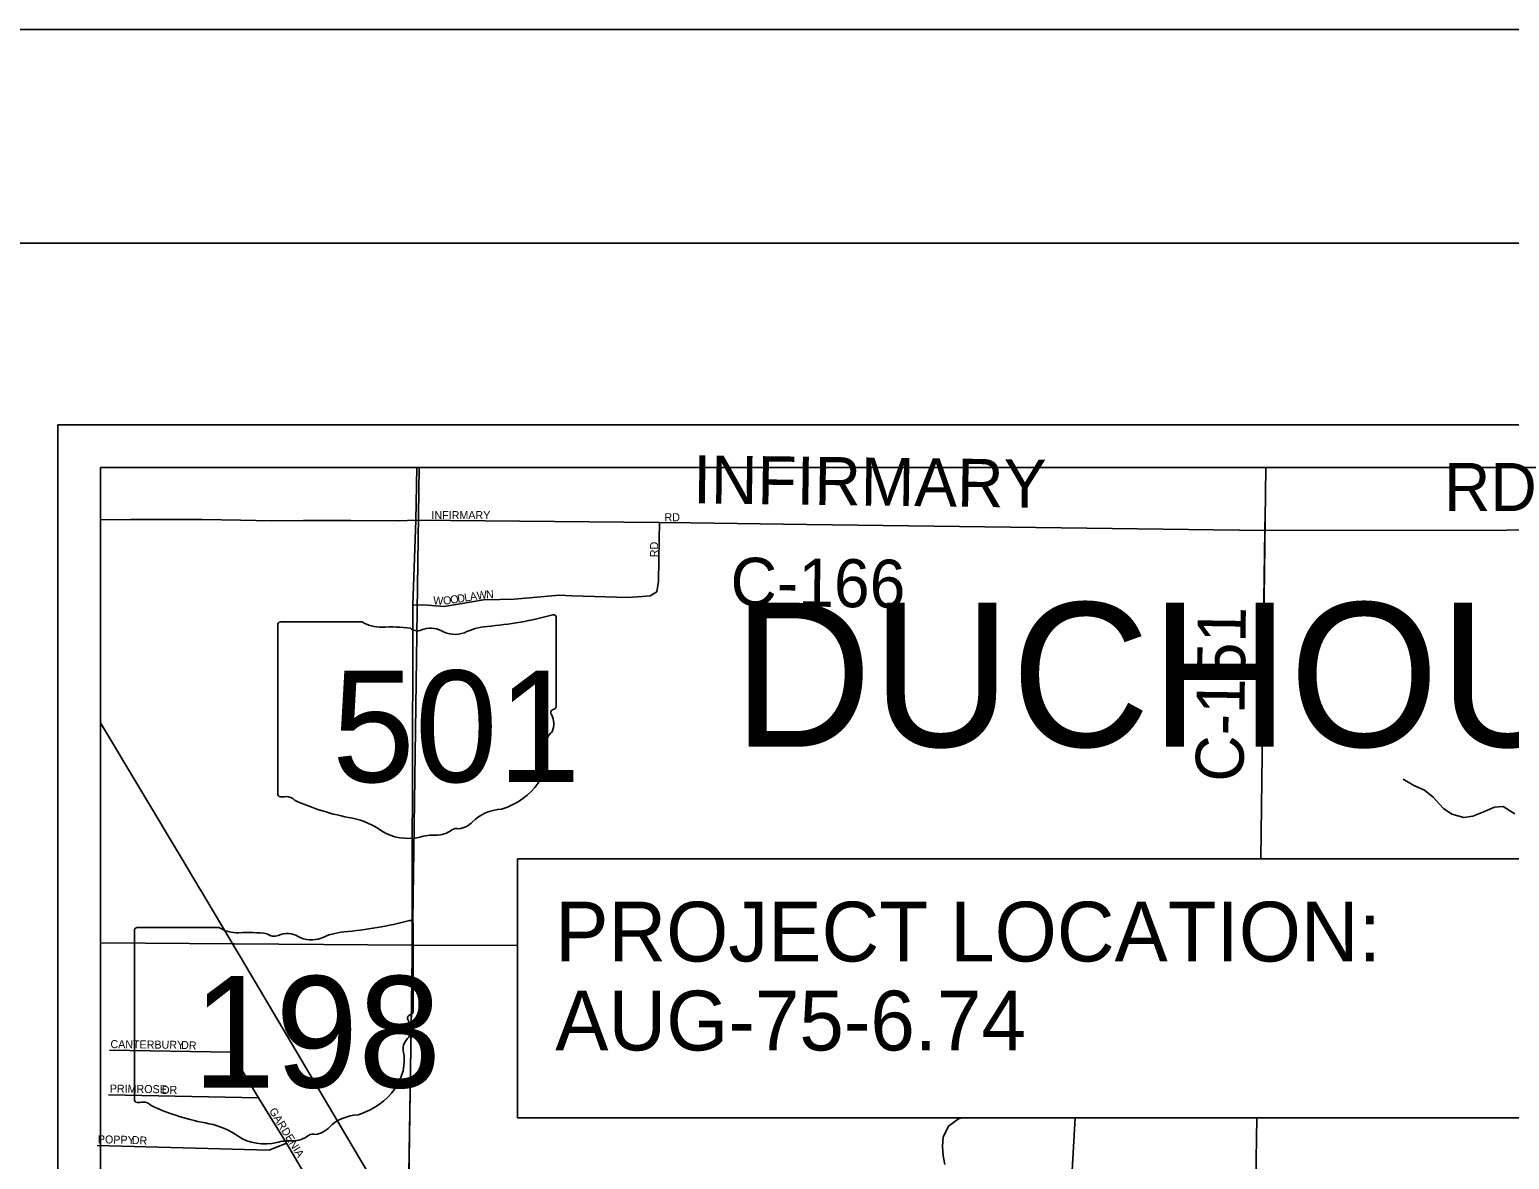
# Model space of a CAD drawing. Extents: x -784 to 1375, y -225 to 440.
# Drawn here: x 63.8 to 133.1, y 387.1 to 440 of the extents above; entities that cross this region are included whole.
import ezdxf

# ---------------------------------------------------------------- set-up
doc = ezdxf.new("R2010")
doc.units = 0
for name, color, linetype in [('GM_X_City_Street', 7, 'Continuous'), ('GM_X_City_Street_Text', 7, 'Continuous'), ('GM_X_County_Road', 7, 'Continuous'), ('GM_X_County_Road_Text', 7, 'Continuous'), ('GM_X_Minor_River', 7, 'Continuous'), ('GM_X_Section', 7, 'Continuous'), ('GM_X_State_Location', 7, 'Continuous'), ('GM_X_State_Route', 7, 'Continuous'), ('GM_X_State_Shield', 7, 'Continuous'), ('GM_X_Township_Text', 7, 'Continuous'), ('SH_Border', 7, 'Continuous'), ('SH_Cut_Line', 7, 'Continuous'), ('SH_Data', 7, 'Continuous'), ('SH_Text', 7, 'Continuous')]:
    doc.layers.add(name, color=color, linetype=linetype)

msp = doc.modelspace()

# ---------------------------------------------------------------- linework, layer by layer
at = {"layer": 'GM_X_City_Street'}
for points in [[(81.06, 416.992), (81.861, 417.014)], [(81.721, 413.038), (82.22, 413.047), (83.192, 412.978), (83.938, 413.102), (85.024, 413.284), (85.799, 413.305), (86.464, 413.316), (87.718, 413.425), (88.569, 413.502), (89.19, 413.469), (91.799, 413.399), (92.473, 413.447), (92.844, 413.48), (93.161, 413.665), (93.226, 414.167), (93.27, 416.098), (93.281, 416.916)], [(81.861, 417.014), (81.861, 417.014), (91.612, 416.93)], [(91.612, 416.93), (93.281, 416.916), (94.732, 416.896)], [(67.507, 392.196), (73.204, 392.102)], [(78.997, 382.464), (77.542, 384.845), (75.795, 387.841), (74.481, 389.954), (73.204, 392.102)], [(67.448, 390.092), (74.481, 389.954)], [(112.107, 376.784), (112.133, 377.221), (112.296, 380.735), (112.591, 386.006), (112.762, 389.014)], [(66.931, 387.726), (74.98, 387.509), (75.795, 387.841)]]:
    msp.add_lwpolyline(points, dxfattribs=at)
at = {"layer": 'GM_X_County_Road'}
for points in [[(67.088, 417.032), (68.489, 417.046), (71.597, 417.057), (71.842, 417.052)], [(71.842, 417.052), (73.637, 417.014), (75.088, 416.981), (76.593, 417.003), (78.818, 417.003), (81.043, 416.992), (81.06, 416.992)], [(94.732, 416.896), (100.192, 416.823)], [(100.192, 416.823), (121.642, 416.536)], [(121.642, 416.536), (121.649, 416.944)], [(121.512, 406.704), (121.513, 406.783), (121.642, 416.536)], [(121.642, 416.536), (155.683, 416.584)]]:
    msp.add_lwpolyline(points, dxfattribs=at)
at = {"layer": 'GM_X_Minor_River'}
for points in [[(133.369, 403.256), (132.818, 403.609), (132.412, 403.569), (131.868, 403.336), (131.4, 403.148), (130.978, 403.093), (130.41, 403.251), (130.023, 403.512), (129.534, 404.044), (129.133, 404.364), (128.625, 404.582), (128.134, 404.889)], [(106.651, 386.832), (106.581, 387.238), (106.542, 387.689), (106.578, 388.109), (106.825, 388.631), (107.296, 388.97), (107.444, 389.014)]]:
    msp.add_lwpolyline(points, dxfattribs=at)
at = {"layer": 'GM_X_Section'}
for p, q in [((121.69, 419.485), (121.464, 401.16)), ((121.464, 401.16), (121.69, 419.485))]:
    msp.add_line(p, q, dxfattribs=at)
for points in [[(82.01, 419.485), (81.709, 397.114), (67.088, 397.216)], [(86.63, 397.087), (81.709, 397.114), (82.01, 419.485)], [(67.088, 397.216), (81.709, 397.114), (81.068, 357.283), (71.441, 357.464), (71.653, 357.594), (72.121, 357.736), (72.758, 358.099), (73.273, 358.374), (73.924, 358.677), (74.439, 358.982), (75.353, 359.701), (76.082, 360.182), (77.094, 360.568), (77.592, 360.724), (77.925, 360.897), (78.122, 386.365), (67.088, 386.554)], [(121.281, 389.014), (120.755, 357.05), (81.068, 357.283), (81.709, 397.114), (86.63, 397.087)], [(133.637, 396.836), (161.159, 396.705), (160.697, 356.887), (120.755, 357.05), (121.281, 389.014)]]:
    msp.add_lwpolyline(points, dxfattribs=at)
at = {"layer": 'GM_X_State_Route'}
for p, q in [((81.875, 417.813), (81.905, 419.485)), ((70.956, 401.053), (67.088, 407.532))]:
    msp.add_line(p, q, dxfattribs=at)
for points in [[(81.717, 411.456), (81.718, 411.633), (81.721, 413.038), (81.861, 417.014), (81.875, 417.813)], [(81.691, 400.382), (81.717, 411.236), (81.717, 411.456)], [(71.768, 399.694), (71.754, 399.717), (70.956, 401.053)], [(81.689, 399.591), (81.69, 400.054), (81.69, 400.116), (81.691, 400.382)], [(73.39, 396.974), (71.768, 399.694)], [(81.683, 396.823), (81.689, 399.321), (81.689, 399.591)], [(81.494, 383.378), (81.206, 383.768), (73.671, 396.504), (73.39, 396.974)], [(81.494, 383.378), (81.51, 384.972), (81.682, 396.541), (81.683, 396.823)]]:
    msp.add_lwpolyline(points, dxfattribs=at)
at = {"layer": 'GM_X_State_Shield'}
for p, q in [((75.389, 412.117), (75.389, 404.193)), ((79.34, 412.254), (75.517, 412.254)), ((88.44, 408.304), (88.44, 412.45)), ((88.439, 408.305), (88.44, 408.304)), ((81.727, 393.993), (81.727, 398.138)), ((68.675, 397.805), (68.675, 389.881)), ((72.626, 397.942), (68.804, 397.942)), ((81.726, 393.994), (81.727, 393.993))]:
    msp.add_line(p, q, dxfattribs=at)
for centre, major_axis, start_param, end_param in [((75.538, 412.134), (0.151, 0), 1.712693, 3.28349), ((80.25, 413.174), (1.467, 0), 4.042523, 4.731795), ((80.736, 407.805), (5.265, 0), 1.404758, 1.657858), ((82.552, 411.259), (0.88, 0), 0.950623, 2.079405), ((85.557, 409.833), (2.785, 0), 1.699011, 2.107814), ((83.791, 423.058), (13.841, 0), 4.814394, 5.042369), ((88.296, 412.467), (0.145, 0), 6.141152, 7.989035), ((81.931, 412.175), (0.423, 0), 3.836095, 5.185415), ((83.688, 412.516), (1.058, 0), 4.081561, 5.145723), ((88.407, 408), (0.225, 0), 1.883978, 3.671073), ((86.976, 407.476), (1.35, 0), 5.934695, 6.695948), ((88.285, 408.288), (0.155, 0), 5.05454, 6.418171), ((84.567, 406.042), (3.462, 0), 5.101752, 6.440018), ((88.961, 406.57), (0.982, 0), 2.387724, 3.262537), ((75.54, 404.175), (0.153, 0), 3.00124, 4.508301), ((75.563, 404.986), (1.164, 0), 4.665946, 4.897461), ((75.801, 403.735), (0.42, 0), 0.519207, 1.627899), ((81.1, 410.855), (9.995, 0), 4.195997, 4.488961), ((78.121, 400.632), (3.127, 0), 0.823519, 1.323587), ((86.026, 401.968), (1.896, 0), 1.647645, 2.488434), ((81.503, 403.696), (1.984, 0), 4.026481, 4.996735), ((82.65, 400.956), (1.631, 0), 1.495662, 1.94098), ((82.794, 403.103), (1.057, 0), 4.691044, 5.507374), ((83.751, 402.335), (0.298, 0), 1.147584, 2.315152), ((83.624, 403.424), (1.118, 0), 4.937069, 5.64225), ((77.078, 408.746), (13.841, 0), 4.814394, 5.042369), ((81.582, 398.155), (0.145, 0), 6.141152, 7.989035), ((68.825, 397.822), (0.151, 0), 1.712693, 3.28349), ((73.536, 398.862), (1.467, 0), 4.042523, 4.731795), ((74.023, 393.493), (5.265, 0), 1.404758, 1.657858), ((75.218, 397.863), (0.423, 0), 3.836095, 5.185415), ((75.839, 396.947), (0.88, 0), 0.950623, 2.079405), ((76.974, 398.204), (1.058, 0), 4.081561, 5.145723), ((78.843, 395.521), (2.785, 0), 1.699011, 2.107814), ((81.572, 393.977), (0.155, 0), 5.05454, 6.418171), ((81.693, 393.688), (0.225, 0), 1.883978, 3.671073), ((80.263, 393.164), (1.35, 0), 5.934695, 6.695948), ((82.248, 392.258), (0.982, 0), 2.387724, 3.262537), ((77.853, 391.73), (3.462, 0), 5.101752, 6.440018), ((68.826, 389.863), (0.153, 0), 3.00124, 4.508301), ((68.849, 390.674), (1.164, 0), 4.665946, 4.897461), ((69.088, 389.424), (0.42, 0), 0.519207, 1.627899), ((74.387, 396.544), (9.995, 0), 4.195997, 4.488961), ((79.313, 387.656), (1.896, 0), 1.647645, 2.488434), ((71.407, 386.32), (3.127, 0), 0.823519, 1.323587), ((76.911, 389.113), (1.118, 0), 4.937069, 5.64225), ((74.79, 389.384), (1.984, 0), 4.026481, 4.996735), ((75.936, 386.644), (1.631, 0), 1.495662, 1.94098), ((76.081, 388.791), (1.057, 0), 4.691044, 5.507374), ((77.038, 388.023), (0.298, 0), 1.147584, 2.315152)]:
    msp.add_ellipse(centre, major_axis=major_axis, ratio=0.8, start_param=start_param, end_param=end_param, dxfattribs=at)
at = {"layer": 'SH_Border'}
msp.add_lwpolyline([(30, 430), (670, 430), (670, 10), (30, 10)], close=True, dxfattribs=at)
at = {"layer": 'SH_Cut_Line'}
msp.add_lwpolyline([(0, 0), (680, 0), (680, 440), (0, 440)], close=True, dxfattribs=at)
at = {"layer": 'SH_Data'}
for q in [(205.088, 421.485), (65.088, 281.485)]:
    msp.add_line((65.088, 421.485), q, dxfattribs=at)
at = {"layer": 'SH_Text'}
for points in [[(67.088, 419.485), (203.088, 419.485), (203.088, 283.485), (67.088, 283.485)], [(86.63, 401.16), (133.637, 401.16), (133.637, 389.014), (86.63, 389.014)]]:
    msp.add_lwpolyline(points, close=True, dxfattribs=at)

# ---------------------------------------------------------------- texts
at = {"layer": 'GM_X_City_Street_Text'}
for s, rotation, p in [('INFIRMARY', 0.00001, (82.592, 417.068)), ('RD', 0.00001, (93.515, 416.969)), ('RD', 90, (93.214, 415.283)), ('W', 357.22491, (82.664, 413.076)), ('O', 6.16436, (83.156, 413.057)), ('O', 9.08508, (83.505, 413.096)), ('D', 9.09825, (83.831, 413.148)), ('L', 9.08056, (84.157, 413.2)), ('A', 9.0851, (84.418, 413.242)), ('W', 7.21468, (84.74, 413.293)), ('N', 3.36774, (85.159, 413.347)), ('CANTERBURY', 359.38851, (67.545, 392.287)), ('DR', 356.98842, (70.848, 392.253)), ('PRIMROSE', 359.17014, (67.512, 390.207)), ('DR', 0.00001, (69.953, 390.141)), ('GARDENIA', 301.50369, (74.964, 389.348)), ('POPPY', 358.66849, (66.952, 387.832)), ('DR', 356.98842, (68.538, 387.798))]:
    msp.add_text(s, height=0.375, rotation=rotation, dxfattribs=at).set_placement(p)
at = {"layer": 'GM_X_County_Road_Text'}
for s, rotation, p in [('INFIRMARY', 359.26589, (94.847, 417.81)), ('RD', 0.00001, (130.046, 417.447)), ('C-166', 359.17413, (96.594, 413.024)), ('C-151', 89.17307, (120.647, 404.753))]:
    msp.add_text(s, height=2.25, rotation=rotation, dxfattribs=at).set_placement(p)
at = {"layer": 'GM_X_State_Location'}
for s in ['s', 'r']:
    msp.add_text(s, height=0.0075, dxfattribs=at).set_placement((67.222, 406.435))
at = {"layer": 'GM_X_State_Shield'}
for s, p in [('501', (77.93, 404.751)), ('198', (71.395, 390.44))]:
    msp.add_text(s, height=5.2207, dxfattribs=at).set_placement(p)
at = {"layer": 'GM_X_Township_Text'}
msp.add_text('DUCHOUQUET', height=6.75, rotation=0.00001, dxfattribs=at).set_placement((96.718, 406.407))
at = {"layer": 'SH_Text'}
for s, p in [('PROJECT LOCATION:', (88.391, 396.344)), ('AUG-75-6.74', (88.391, 392.177))]:
    msp.add_text(s, height=2.8, dxfattribs=at).set_placement(p)

doc.saveas('drawing.dxf')
